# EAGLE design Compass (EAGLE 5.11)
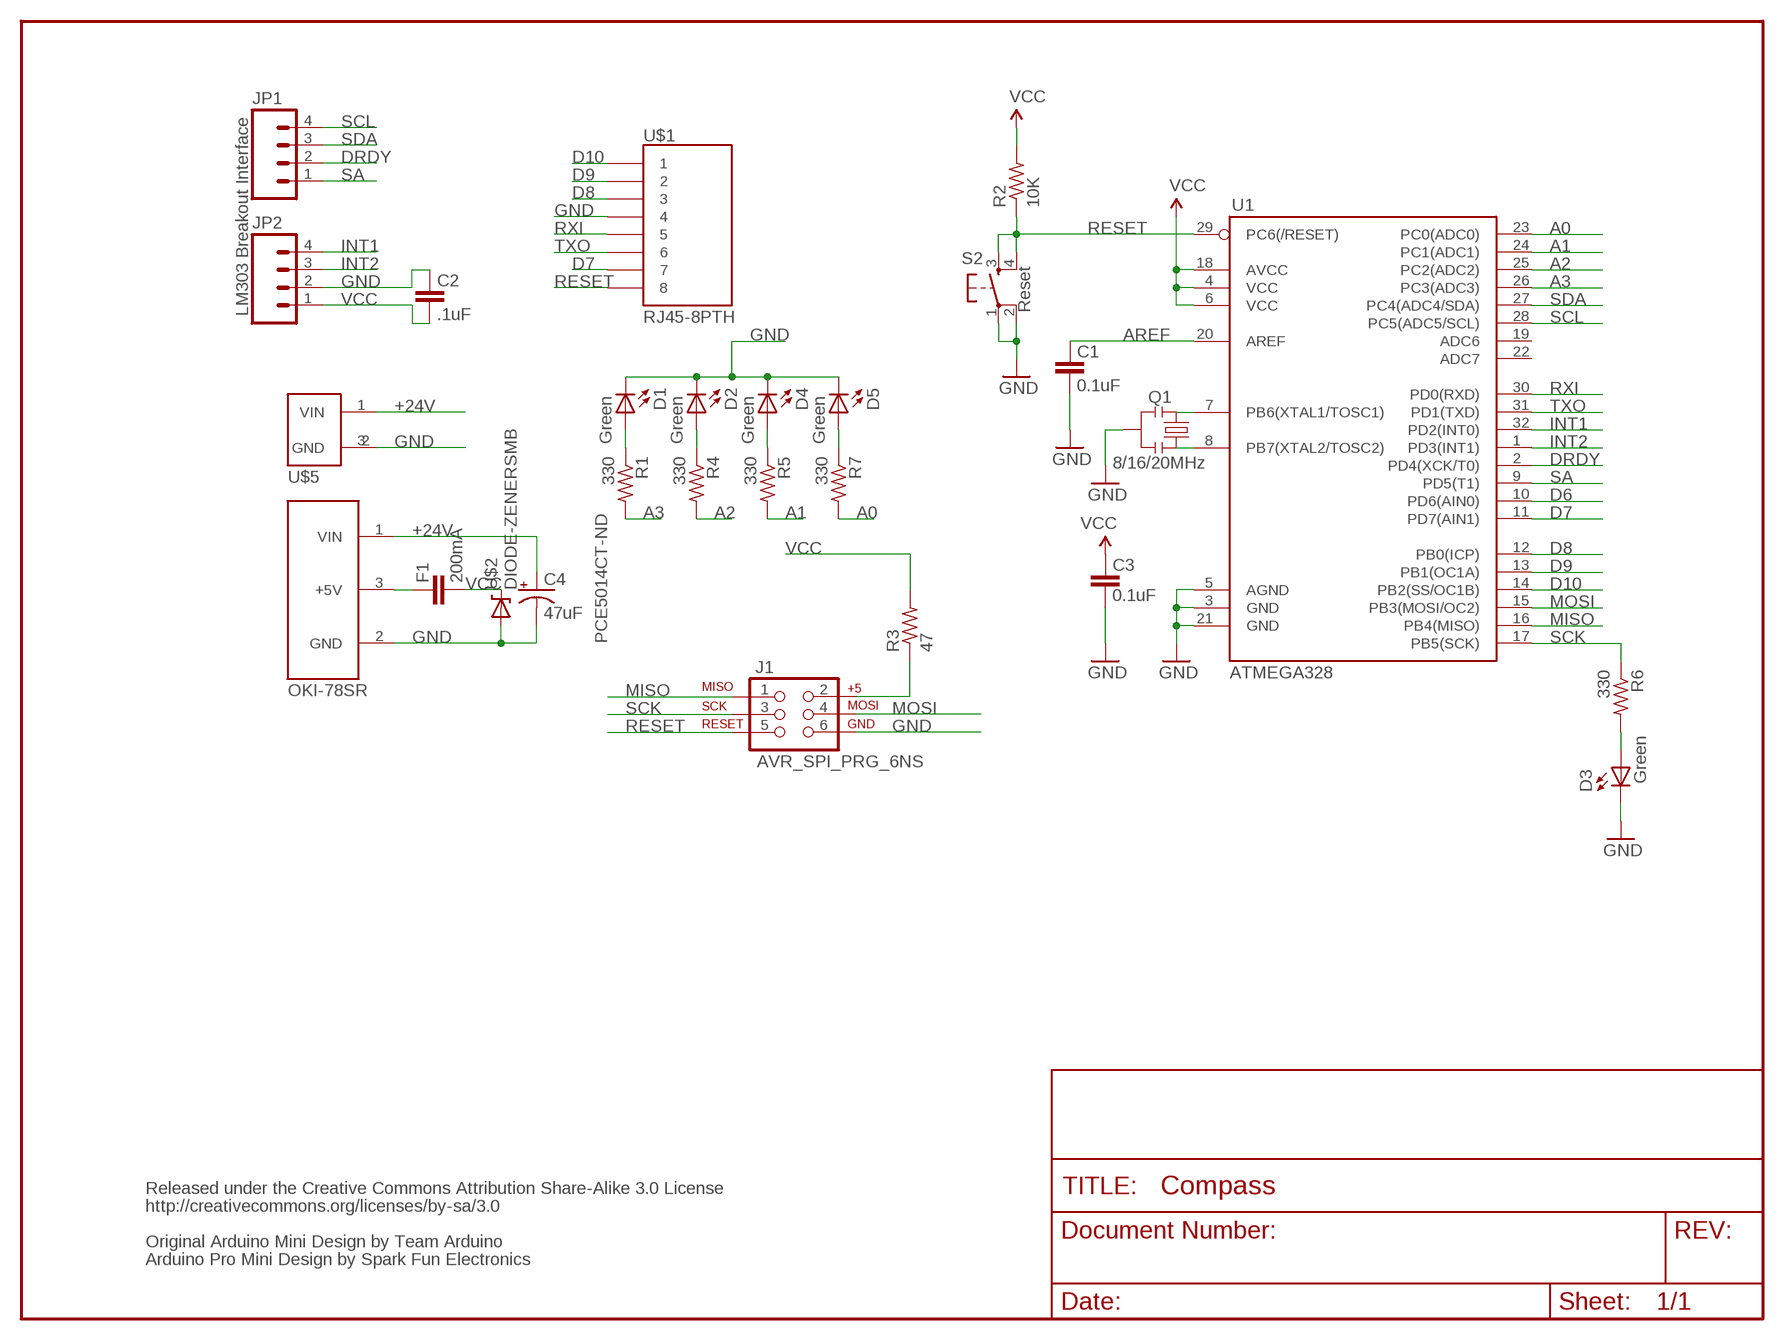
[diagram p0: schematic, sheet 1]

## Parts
C1  0.1uF  C-EUC0603  [C0603]
C2  .1uF  C-EUC0603  [C0603]
C3  0.1uF  C-EUC0603  [C0603]
C4  47uF  CPOL-US153CLV-0405  [153CLV-0405]
D1  Green  LED0603  [LED-0603]
D2  Green  LED0603  [LED-0603]
D3  Green  LED0603  [LED-0603]
D4  Green  LED0603  [LED-0603]
D5  Green  LED0603  [LED-0603]
F1  200mA  C-EUC0603  [C0603]
J1  AVR_SPI_PRG_6NS  [2X3-NS]
JP1  M041X04_NO_SILK  [1X04_NO_SILK]
JP2  M041X04_NO_SILK  [1X04_NO_SILK]
Q1  8/16/20MHz  RESONATORSMD  [RESONATOR-SMD]
R1  330  R-US_R0603  [R0603]
R2  10K  R-US_R0603  [R0603]
R3  47  R-US_R0603  [R0603]
R4  330  R-US_R0603  [R0603]
R5  330  R-US_R0603  [R0603]
R6  330  R-US_R0603  [R0603]
R7  330  R-US_R0603  [R0603]
S2  Reset  TAC_SWITCHSMD  [TACTILE_SWITCH_SMD]
U1  ATMEGA328  ATMEGA168  [TQFP32-08]
U$1  RJ45-8PTH  [RJ45-8]
U$2  DIODE-ZENERSMB  [SMB-DIODE]
U$3  BARREL-3.5MM  [BARREL-3.5MM]
U$5  OKI-78SR  [SIP-3]

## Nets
+24V: C4.+ U$3.1(VIN) U$5.1(VIN)
A0: R7.2 U1.23(PC0(ADC0))
A1: R5.2 U1.24(PC1(ADC1))
A2: R4.2 U1.25(PC2(ADC2))
A3: R1.2 U1.26(PC3(ADC3))
AREF: C1.2 U1.20(AREF)
D6: U1.10(PD6(AIN0))
D7: U1.11(PD7(AIN1)) U$1.7
D8: U1.12(PB0(ICP)) U$1.3
D9: U1.13(PB1(OC1A)) U$1.2
D10: U1.14(PB2(SS/OC1B)) U$1.1
DRDY: JP1.2 U1.2(PD4(XCK/T0))
GND [vcc]: C1.1 C2.2 C3.1 C4.- D1.C D2.C D3.C D4.C D5.C J1.6 JP2.2 Q1.2 S2.1 S2.2 U1.3(GND) U1.5(AGND) U1.21(GND) U$1.4 U$2.A U$3.3(GND) U$5.2(GND)
INT1: JP2.4 U1.32(PD2(INT0))
INT2: JP2.3 U1.1(PD3(INT1))
MISO: J1.1 U1.16(PB4(MISO))
MOSI: J1.4 U1.15(PB3(MOSI/OC2))
N$1: Q1.1 U1.8(PB7(XTAL2/TOSC2))
N$2: Q1.3 U1.7(PB6(XTAL1/TOSC1))
N$3: D1.A R1.1
N$4: D2.A R4.1
N$5: D4.A R5.1
N$6: J1.2 R3.1
N$7: D3.A R6.2
N$8: D5.A R7.1
N$9: F1.2 U$5.3(+5V)
RESET: J1.5 R2.1 S2.3 S2.4 U1.29(PC6(/RESET)) U$1.8
RXI: U1.30(PD0(RXD)) U$1.5
SA: JP1.1 U1.9(PD5(T1))
SCK: J1.3 R6.1 U1.17(PB5(SCK))
SCL: JP1.4 U1.28(PC5(ADC5/SCL))
SDA: JP1.3 U1.27(PC4(ADC4/SDA))
TXO: U1.31(PD1(TXD)) U$1.6
VCC: C2.1 C3.2 F1.1 JP2.1 R2.2 R3.2 U1.4(VCC) U1.6(VCC) U1.18(AVCC) U$2.C
Unconnected: U1.19(ADC6) U1.22(ADC7) U$3.2(GND__)

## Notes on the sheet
- LM303 Breakout Interface
- PCE5014CT-ND
- Released under the Creative Commons Attribution Share-Alike 3.0 License
- http://creativecommons.org/licenses/by-sa/3.0
- Original Arduino Mini Design by Team Arduino
- Arduino Pro Mini Design by Spark Fun Electronics

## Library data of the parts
C1-C3 F1 = resistor:C-EU: CAPACITOR, European symbol
C4 = resistor:CPOL-US: POLARIZED CAPACITOR, American symbol
D1-D5 = SparkFun:LED: LEDs
J1 = SparkFun:AVR_SPI_PRG_6: AVR ISP 6 Pin This is the reduced ISP connector for AVR programming. Common on Arduino. This footprint will take up less PCB space and can be used with a 10-pin to 6-pin adapter such as SKU: BOB-08508
JP1 JP2 = SparkFun:M04: Header 4 Standard 4-pin 0.1" header. Use with straight break away headers (SKU : PRT-00116), right angle break away headers (PRT-00553), swiss pins (PRT-00743), machine pins (PRT-00117), and female headers (PRT-00115). Molex polarized connector foot print use with SKU : PRT-08231 with associated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
Q1 = SparkFun:RESONATOR: Resonator Small SMD resonator. This is the itty bitty 10/20MHz resonators with built in caps. CSTCE10M0G55 and CSTCE20M0V53. Footprint has been reviewed closely but hasn't been tested yet.
R1-R7 = resistor:R-US_: RESISTOR, American symbol
S2 = SparkFun:TAC_SWITCH: Momentary Switch Button commonly used for reset or general input. Spark Fun Electronics SKU : COM-00097
U1 = SparkFun:ATMEGA168
U$1 = SparkFun:RJ45-8: RJ45 Jack Simple RJ45, 8-pin connection - connector for common Cat5, Cat5e, and Cat6 Ethernet cables. Footprint not yet proven in production. Connector sku is PRT-00643; Breakout PCB sku is BOB-00716.
U$2 = SparkFun:DIODE-ZENER: Zener Diode
U$3 = #ROBO-Tutorial:BARREL-3.5MM
U$5 = #ROBO-Tutorial:OKI-78SR

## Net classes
0 default: width 0.203 mm
1 vcc: width 0.254 mm

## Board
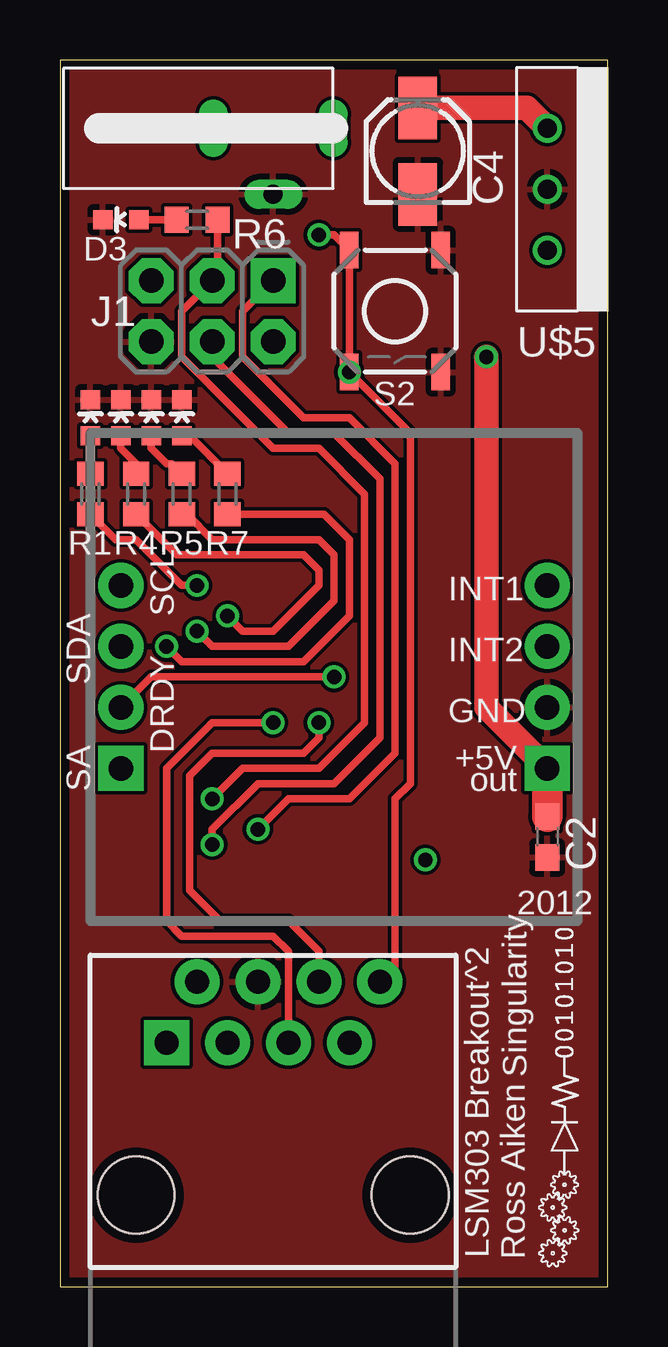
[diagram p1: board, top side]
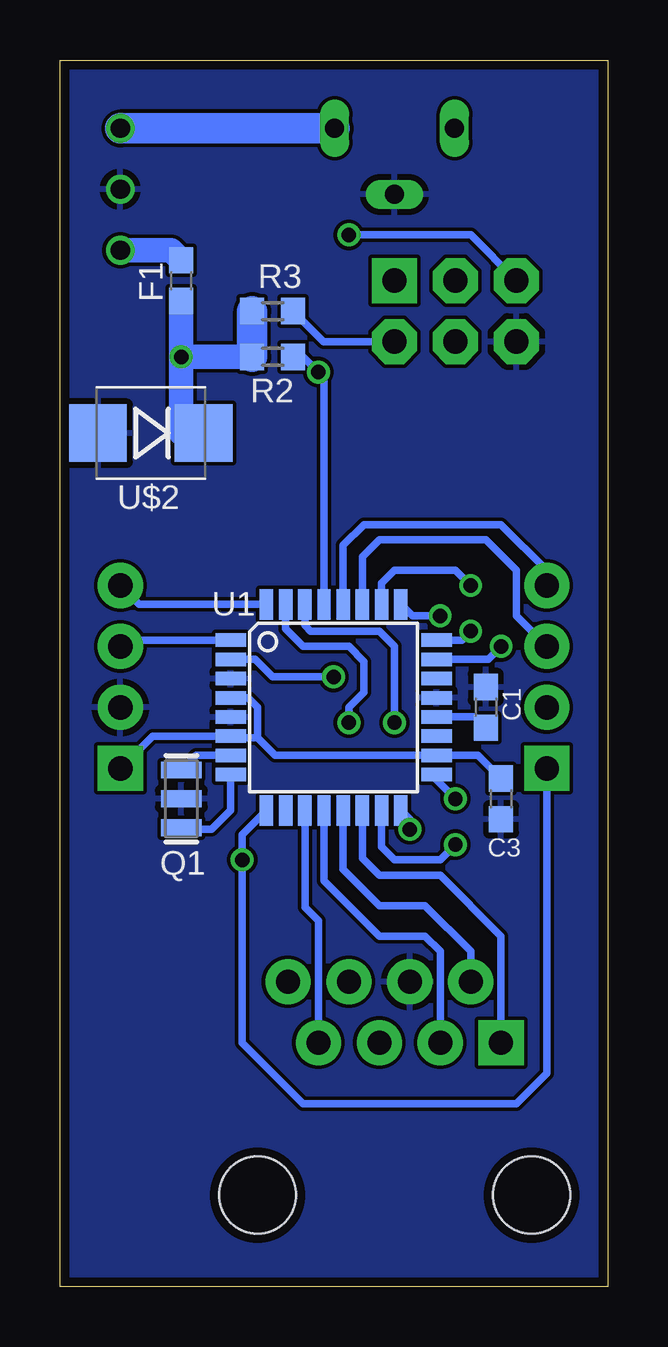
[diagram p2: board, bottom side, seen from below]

Size 22.84 x 51.1 mm. Coordinates in mm from the lower left corner, seen from the top.
Outline: 0,0 22.84,0 22.84,51.1 0,51.1 0,0
Copper layers (1*16): Top 0.0356mm / dielectric 1.5011mm / Bottom 0.0356mm
Design rules "default": minimum track width 6mil, minimum drill 13mil, track to track 6mil, track to pad 6mil, pad to pad 6mil, via to via 6mil, smd to smd 0mil, copper to edge 15mil, drill to drill 6mil, minimum pad ring 7mil, minimum via ring 7mil, stop-mask expansion 4mil, vias tented up to drill 0mil, thermal gap 10mil

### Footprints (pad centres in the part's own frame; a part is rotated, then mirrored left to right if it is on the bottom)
C0603 = smd 1.1 x 1: 1 -0.85,0; 2 0.85,0
153CLV-0405 = smd 2.6 x 1.6: + 1.8,0; - -1.8,0
LED-0603 = smd 0.8 x 0.8: A 0,-0.75; C 0,0.75
2X3-NS = drill 1.016 pad 1.88 square: 1 -2.54,-1.27 | drill 1.016 pad 1.88 octagon: 2 -2.54,1.27; 3 0,-1.27; 4 0,1.27; 5 2.54,-1.27; 6 2.54,1.27
1X04_NO_SILK = drill 1.016 pad 1.88 square: 1 0,0 | drill 1.016 pad 1.88 round: 2 2.54,0; 3 5.08,0; 4 7.62,0
RESONATOR-SMD = smd 0.7 x 1.7: 1 -1.2,0; 2 0,0; 3 1.2,0
R0603 = smd 1 x 1.1: 1 -0.85,0; 2 0.85,0
TACTILE_SWITCH_SMD = smd 1.524 x 0.762: 1 -2.54,1.905; 2 2.54,1.905; 3 -2.54,-1.905; 4 2.54,-1.905
TQFP32-08 = smd 1.27 x 0.559: 1 -4.293,2.8; 2 -4.293,2; 3 -4.293,1.2; 4 -4.293,0.4; 5 -4.293,-0.4; 6 -4.293,-1.2; 7 -4.293,-2; 8 -4.293,-2.8; 17 4.293,-2.8; 18 4.293,-2; 19 4.293,-1.2; 20 4.293,-0.4; 21 4.293,0.4; 22 4.293,1.2; 23 4.293,2; 24 4.293,2.8 | smd 0.559 x 1.27: 9 -2.8,-4.293; 10 -2,-4.293; 11 -1.2,-4.293; 12 -0.4,-4.293; 13 0.4,-4.293; 14 1.2,-4.293; 15 2,-4.293; 16 2.8,-4.293; 25 2.8,4.293; 26 2,4.293; 27 1.2,4.293; 28 0.4,4.293; 29 -0.4,4.293; 30 -1.2,4.293; 31 -2,4.293; 32 -2.8,4.293
RJ45-8 = drill 1 pad 1.88 square: 1 -4.445,6.35 | drill 1 pad 1.88 round: 2 -3.175,8.89; 3 -1.905,6.35; 4 -0.635,8.89; 5 0.635,6.35; 6 1.905,8.89; 7 3.175,6.35; 8 4.445,8.89 | hole 3.2: -5.715,0; 5.715,0
SMB-DIODE = smd 2.4 x 2.4: A 2.2,0; C -2.2,0
BARREL-3.5MM = drill 0.8 long: 1 2.5,0; 2 -2.5,0; 3 0,-2.75
SIP-3 = drill 0.8 round: 1 -2.54,0; 2 0,0; 3 2.54,0

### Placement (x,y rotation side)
C1  5.08,24.13 270 bottom
C2  20.32,18.73 270 top
C3  4.45,20.32 90 bottom
C4  14.92,47.31 90 top
D1  1.27,36.2 0 top
D2  2.54,36.2 0 top
D3  2.54,44.45 90 top
D4  3.81,36.2 0 top
D5  5.08,36.2 0 top
F1  17.78,41.91 90 bottom
J1  6.35,40.64 180 top
JP1  2.54,21.59 90 top
JP2  20.32,21.59 90 top
Q1  17.78,20.32 90 bottom
R1  1.27,33.02 270 top
R2  13.97,38.73 180 bottom
R3  13.97,40.64 180 bottom
R4  3.17,33.02 270 top
R5  5.08,33.02 270 top
R6  5.71,44.45 180 top
R7  6.99,33.02 270 top
S2  13.97,40.64 270 top
U1  11.43,24.13 0 bottom
U$1  8.89,3.81 0 top
U$2  19.05,35.56 180 bottom
U$3  8.89,48.26 0 top
U$5  20.32,45.72 270 top

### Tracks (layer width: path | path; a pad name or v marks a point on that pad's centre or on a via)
+24V
  Top 1.016: C4.+ 19.47,49.11 U$5.1
  Bottom 1.27: U$3.1 U$5.1
A0  (via drill 0.6)
  Top 0.305: R7.2 11.01,32.17 12.06,31.11 12.06,27.94 10.16,26.04 5.08,26.04 v4.45,26.67
  Bottom 0.305: U1.23 4.99,26.13 v4.45,26.67
A1  (via drill 0.6)
  Top 0.305: R5.2 5.29,32.17 6.35,31.11 10.79,31.11 11.43,30.48 11.43,28.57 9.53,26.67 6.35,26.67 v5.71,27.3
  Bottom 0.305: v5.71,27.3 6.09,26.93 U1.24
A2  (via drill 0.6)
  Top 0.305: R4.2 4.87,30.48 10.16,30.48 10.79,29.84 10.79,29.21 8.89,27.3 7.62,27.3 v6.99,27.94
  Bottom 0.305: v6.99,27.94 8.15,27.94 U1.25
A3  (via drill 0.6)
  Top 0.305: R1.2 2.33,31.11 3.17,31.11 5.08,29.21 v5.71,29.21
  Bottom 0.305: v5.71,29.21 6.35,29.84 8.89,29.84 9.43,29.3 U1.26
AREF
  Bottom 0.305: C1.2 5.53,23.73 U1.20
D7
  Bottom 0.305: U1.11 12.63,15.8 12.06,15.24 U$1.7
D8
  Bottom 0.305: U1.12 11.83,16.91 9.53,14.61 7.62,14.61 6.99,13.97 U$1.3
D9
  Bottom 0.305: U1.13 11.03,17.38 9.53,15.88 7.62,15.88 5.71,13.97 U$1.2
D10
  Bottom 0.305: U1.14 10.23,17.85 9.53,17.14 6.99,17.14 4.45,14.61 U$1.1
DRDY  (via drill 0.6)
  Top 0.305: JP1.2 3.81,25.4 v11.43,25.4
  Bottom 0.305: v11.43,25.4 13.97,25.4 14.7,26.13 U1.2
GND
  pour Bottom (isolate 0.152): 0,51.44 22.86,51.44 22.86,0 0,0
  pour Top (isolate 0.152): 0,51.44 22.86,51.44 22.86,0 0,0
INT1
  Bottom 0.305: U1.32 19.53,28.42 JP2.4
INT2
  Bottom 0.305: U1.1 20.06,26.93 JP2.3
MISO  (via drill 0.6)
  Top 0.305: v8.26,19.05 9.53,20.32 12.06,20.32 13.97,22.23 13.97,34.29 12.06,36.2 10.16,36.2 7.62,38.73 7.62,40.64 J1.1
  Bottom 0.305: U1.16 8.26,19.46 v8.26,19.05
MOSI  (via drill 0.6)
  Top 0.305: v6.35,18.41 6.35,19.05 8.26,20.95 11.43,20.95 13.34,22.86 13.34,33.66 11.43,35.56 9.53,35.56 6.35,38.73 J1.4
  Bottom 0.305: U1.15 9.43,18.32 8.89,17.78 6.99,17.78 v6.35,18.41
N$1
  Bottom 0.305: U1.8 15.72,19.84 16.51,19.05 17.71,19.05 Q1.1
N$2
  Bottom 0.305: U1.7 17.17,22.13 Q1.3
N$3
  Top 0.305: D1.A R1.1
N$4
  Top 0.305: D2.A 2.54,34.92 3.17,34.29 R4.1
N$5
  Top 0.305: D4.A 3.81,34.92 4.45,34.29 4.66,34.29 R5.1
N$6
  Bottom 0.305: R3.1 11.85,39.37 J1.2
N$7
  Top 0.305: D3.A R6.2
N$8
  Top 0.305: D5.A 5.41,35.45 R7.1
N$9
  Bottom 1.016: U$5.3 18.2,43.18 F1.2
RESET  (via drill 0.6)
  Top 0.305: v10.79,43.81 11.43,43.81 S2.3 v12.06,38.1 14.61,35.56 14.61,20.95 13.97,20.32 13.97,13.34 U$1.8
  Bottom 0.305: R2.1 12.7,38.73 v12.06,38.1 11.83,37.87 U1.29 | J1.5 5.71,43.81 v10.79,43.81
RXI  (via drill 0.6)
  Top 0.305: v8.89,23.5 6.35,23.5 4.45,21.59 4.45,15.24 5.08,14.61 8.89,14.61 9.53,13.97 U$1.5
  Bottom 0.305: U1.30 12.63,27.55 12.38,27.3 9.53,27.3 8.89,26.67 v8.89,23.5
SA  (via drill 0.6)
  Bottom 0.305: U1.9 15.24,18.83 v15.24,17.78 15.24,10.16 12.7,7.62 3.81,7.62 2.54,8.89 JP1.1
SCK  (via drill 0.6)
  Top 0.305: v6.35,20.32 7.62,21.59 10.79,21.59 12.7,23.5 12.7,33.02 10.79,34.92 8.89,34.92 5.08,38.73 5.08,40.64 J1.3 6.57,42.12 R6.1
  Bottom 0.305: U1.17 7.14,21.11 v6.35,20.32
SCL
  Bottom 0.305: U1.28 11.03,30.88 10.16,31.75 4.45,31.75 2.54,29.84 JP1.4
SDA
  Bottom 0.305: JP1.3 3.81,27.94 3.81,29.84 5.08,31.11 9.53,31.11 10.23,30.41 U1.27
TXO  (via drill 0.6)
  Top 0.305: v10.79,23.5 10.79,22.86 10.16,22.23 6.35,22.23 5.4,21.27 5.4,16.51 6.67,15.24 9.53,15.24 10.79,13.97 U$1.6
  Bottom 0.305: U1.31 13.43,27.4 12.7,26.67 10.79,26.67 10.16,26.04 10.16,24.77 10.79,24.13 v10.79,23.5
VCC  (via drill 0.6)
  Top 1.016: v17.78,38.73 17.78,24.13 JP2.1
  Top 1.27: JP2.1 C2.1
  Bottom 0.305: 14.61,22.86 13.88,22.13 U1.18 5.41,22.13 C3.2 | 14.61,22.86 15.65,22.86 U1.6 18.98,22.93 JP2.1 | U1.4 15.01,24.53 14.61,24.13 14.61,22.86
  Bottom 1.016: v17.78,38.73 F1.1 | v17.78,38.73 R2.2 | v17.78,38.73 17.78,35.56 U$2.C
  Bottom 1.27: R2.2 R3.2

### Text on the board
tNames: INT1 | SCL | INT2 | SDA | GND | +5V | DRDY | out | SA | 2012 | Singularity | LSM303 Breakout^2 | Ross Aiken | E:/Users/Ross/Desktop/Logo_nocolor.bmp | E:/Users/Ross/Desktop/Logo_nocolor.bmp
